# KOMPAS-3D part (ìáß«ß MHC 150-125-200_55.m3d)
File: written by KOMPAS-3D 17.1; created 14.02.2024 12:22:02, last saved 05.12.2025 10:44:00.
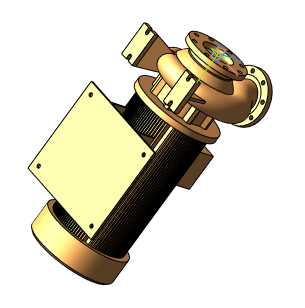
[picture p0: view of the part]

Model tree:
1. Операция без истории:4

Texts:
  ООО АДЛ Групп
